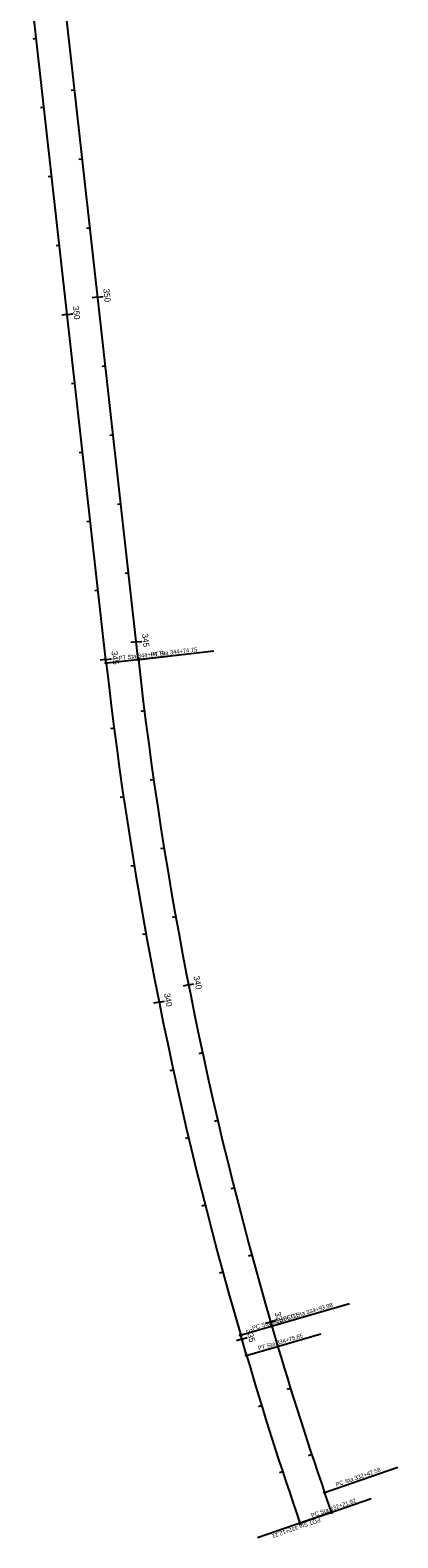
# Model space of a CAD drawing. Extents: x 1602163 to 1612907, y 1087635 to 1096265.
# Drawn here: x 1612378 to 1612907, y 1087635 to 1089807 of the extents above; entities that cross this region are included whole.
import ezdxf

# ---------------------------------------------------------------- set-up
doc = ezdxf.new("R2010")
doc.units = 0
for name, color, linetype in [('RD_HC_Cl', 7, 'Continuous'), ('RD_HC_Data_Tic', 7, 'Continuous'), ('RD_HC_Points', 7, 'Continuous'), ('RD_HC_TX_Sta50', 7, 'Continuous')]:
    doc.layers.add(name, color=color, linetype=linetype)

msp = doc.modelspace()

# ---------------------------------------------------------------- linework, layer by layer
at = {"layer": 'RD_HC_Cl'}
for p, q in [((1612533.6, 1088900.6), (1612380.9, 1090265.1)), ((1612487.4, 1088895.4), (1612377.9, 1089874.1)), ((1612689.6, 1087897.9), (1612681.1, 1087927)), ((1612811.9, 1087671.8), (1612802, 1087700.5))]:
    msp.add_line(p, q, dxfattribs=at)
for centre, radius, start, end in [((1618204.6, 1089535.2), 5752.8, 186.3858, 196.23352), ((1618204.6, 1089535.2), 5706.3, 186.3858, 196.2335), ((1617613.8, 1089363.2), 5091, 196.2335, 199.0628), ((1617623, 1089334.3), 5138.3, 196.2335, 199.0628)]:
    msp.add_arc(centre, radius, start, end, dxfattribs=at)
at = {"layer": 'RD_HC_Data_Tic'}
for p, q in [((1612386.7, 1089795), (1612381.8, 1089794.4)), ((1612441.9, 1089720.7), (1612436.9, 1089720.1)), ((1612397.9, 1089695.6), (1612392.9, 1089695.1)), ((1612453, 1089621.3), (1612448, 1089620.8)), ((1612409, 1089596.2), (1612404, 1089595.7)), ((1612464.1, 1089521.9), (1612459.1, 1089521.4)), ((1612420.1, 1089496.9), (1612415.1, 1089496.3)), ((1612475.2, 1089422.6), (1612467.3, 1089421.7)), ((1612475.2, 1089422.6), (1612483.2, 1089423.4)), ((1612431.2, 1089397.5), (1612423.3, 1089396.6)), ((1612431.2, 1089397.5), (1612439.2, 1089398.4)), ((1612486.3, 1089323.2), (1612481.4, 1089322.6)), ((1612442.4, 1089298.1), (1612437.4, 1089297.5)), ((1612497.5, 1089223.8), (1612492.5, 1089223.2)), ((1612453.5, 1089198.7), (1612448.5, 1089198.2)), ((1612508.6, 1089124.4), (1612503.6, 1089123.9)), ((1612464.6, 1089099.3), (1612459.6, 1089098.8)), ((1612519.7, 1089025), (1612514.7, 1089024.5)), ((1612475.7, 1089000), (1612470.8, 1088999.4)), ((1612530.8, 1088925.7), (1612522.9, 1088924.8)), ((1612530.8, 1088925.7), (1612538.8, 1088926.5)), ((1612486.9, 1088900.6), (1612478.9, 1088899.7)), ((1612486.9, 1088900.6), (1612494.8, 1088901.5)), ((1612542.4, 1088826.3), (1612537.5, 1088825.7)), ((1612498.7, 1088801.3), (1612493.8, 1088800.6)), ((1612555.7, 1088727.2), (1612550.8, 1088726.5)), ((1612512.4, 1088702.2), (1612507.4, 1088701.5)), ((1612570.8, 1088628.4), (1612565.8, 1088627.6)), ((1612527.7, 1088603.4), (1612522.8, 1088602.6)), ((1612587.5, 1088529.8), (1612582.6, 1088528.9)), ((1612544.8, 1088504.9), (1612539.8, 1088504)), ((1612606, 1088431.5), (1612598.1, 1088430)), ((1612606, 1088431.5), (1612613.8, 1088433)), ((1612563.5, 1088406.6), (1612555.7, 1088405.1)), ((1612563.5, 1088406.6), (1612571.4, 1088408.2)), ((1612626.2, 1088333.6), (1612621.3, 1088332.5)), ((1612584, 1088308.8), (1612579.1, 1088307.7)), ((1612648.1, 1088236), (1612643.2, 1088234.9)), ((1612606.2, 1088211.3), (1612601.3, 1088210.1)), ((1612671.7, 1088138.8), (1612666.9, 1088137.6)), ((1612630, 1088114.1), (1612625.2, 1088112.9)), ((1612697.1, 1088042.1), (1612692.2, 1088040.8)), ((1612655.6, 1088017.5), (1612650.7, 1088016.1)), ((1612724.1, 1087945.8), (1612716.4, 1087943.6)), ((1612724.1, 1087945.8), (1612731.7, 1087948)), ((1612682.8, 1087921.2), (1612675.1, 1087919)), ((1612682.8, 1087921.2), (1612690.5, 1087923.5)), ((1612752.8, 1087850), (1612748.1, 1087848.6)), ((1612711.3, 1087825.4), (1612706.5, 1087823.9)), ((1612783.5, 1087754.9), (1612778.8, 1087753.3)), ((1612741.6, 1087730.1), (1612736.8, 1087728.5))]:
    msp.add_line(p, q, dxfattribs=at)
at = {"layer": 'RD_HC_Points'}
for p, q in [((1612534.9, 1088900.7), (1612642.5, 1088912.8)), ((1612488.7, 1088895.5), (1612596.2, 1088907.6)), ((1612682.3, 1087927.4), (1612787.8, 1087958.1)), ((1612726.9, 1087940.4), (1612837.8, 1087972.7)), ((1612690.8, 1087898.2), (1612796.4, 1087929)), ((1612803.1, 1087700.9), (1612907.4, 1087736.9)), ((1612767.7, 1087656.5), (1612869.1, 1087691.5)), ((1612810.7, 1087671.4), (1612705.2, 1087634.9))]:
    msp.add_line(p, q, dxfattribs=at)
for centre in [(1612487.4, 1088895.4), (1612533.6, 1088900.6), (1612725.7, 1087940), (1612681.1, 1087927), (1612689.6, 1087897.9), (1612802, 1087700.5), (1612766.5, 1087656.1), (1612811.9, 1087671.8)]:
    msp.add_circle(centre, 1.25, dxfattribs=at)

# ---------------------------------------------------------------- texts
for s, rotation, p in [('PT Sta 344+94.79', 6.3858, (1612505.8, 1088899.5)), ('PT Sta 344+74.75', 6.3858, (1612552.1, 1088904.6)), ('PC Sta 335+06.02', 16.2335, (1612698.5, 1087934.2)), ('PCC Sta 334+93.98', 16.2335, (1612743.2, 1087947.2)), ('PT Sta 334+75.65', 16.2335, (1612707, 1087905)), ('PC Sta 332+42.58', 19.0628, (1612819, 1087708.5)), ('PC Sta 332+21.92', 19.0628, (1612783.6, 1087664.1)), ('POT Sta 332+12.21', 199.0628, (1612794.8, 1087663.8))]:
    msp.add_text(s, height=6, rotation=rotation, dxfattribs=at).set_placement(p)
at = {"layer": 'RD_HC_TX_Sta50'}
for s, rotation, p in [('350', 276.3858, (1612483.2, 1089434.4)), ('350', 276.3858, (1612439.2, 1089409.3)), ('345', 276.3858, (1612538.8, 1088937.3)), ('345', 276.3858, (1612494.9, 1088912.2)), ('340', 281.1527, (1612613, 1088443.7)), ('340', 281.3137, (1612570.5, 1088418.8)), ('335', 286.173, (1612729.8, 1087959.1)), ('335', 286.2335, (1612688.5, 1087934.6))]:
    msp.add_text(s, height=8.75, rotation=rotation, dxfattribs=at).set_placement(p)

doc.saveas('drawing.dxf')
